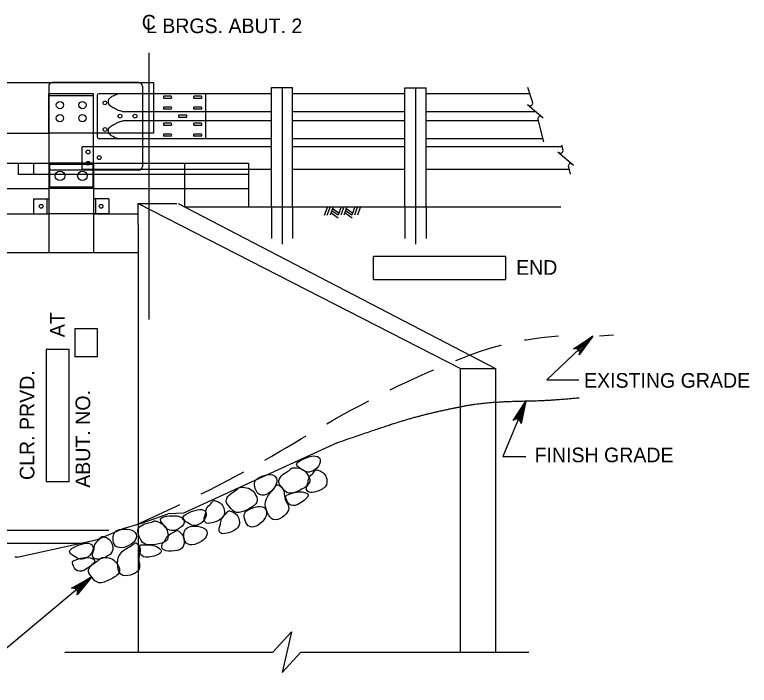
# Model space of a CAD drawing. Extents: x 638268 to 640277, y 295465 to 298435.
# Drawn here: x 638721.7 to 638872.6, y 297975.3 to 298112.9 of the extents above; entities that cross this region are included whole.
import ezdxf

# ---------------------------------------------------------------- set-up
doc = ezdxf.new("R2010")
doc.units = 0
for name, color, linetype in [('2', 7, 'Continuous'), ('3', 7, 'Continuous'), ('4', 7, 'Continuous'), ('8', 7, 'Continuous'), ('Level 25', 7, 'Continuous')]:
    doc.layers.add(name, color=color, linetype=linetype)

msp = doc.modelspace()

# ---------------------------------------------------------------- linework, layer by layer
at = {"layer": '2'}
for p, q in [((638577.23, 298099.02), (638750.23, 298099.02)), ((638747.15, 298099.02), (638729.45, 298099.02)), ((638750.23, 298099.02), (638750.23, 298096.71)), ((638728.68, 298098.25), (638728.68, 298096.7)), ((638747.92, 298098.25), (638747.92, 298096.71)), ((638737.91, 298096.7), (638728.68, 298096.7)), ((638728.68, 298088.62), (638728.68, 298096.7)), ((638737.91, 298096.32), (638728.68, 298096.32)), ((638737.91, 298082.46), (638737.91, 298096.7)), ((638738.65, 298096.35), (638738.65, 298087.85)), ((638750.23, 298096.72), (638739.02, 298096.72)), ((638747.92, 298096.71), (638747.92, 298087.47)), ((638760.82, 298096.72), (638750.23, 298096.72)), ((638750.23, 298096.7), (638750.23, 298088.62)), ((638753.84, 298096.21), (638752.36, 298096.21)), ((638753.84, 298095.75), (638752.36, 298095.75)), ((638760.01, 298096.21), (638758.54, 298096.21)), ((638760.01, 298095.75), (638758.54, 298095.75)), ((638760.88, 298096.72), (638760.88, 298087.48)), ((638774.46, 298096.72), (638760.88, 298096.72)), ((638801.85, 298096.72), (638778.78, 298096.72)), ((638827.47, 298096.72), (638806.18, 298096.72)), ((638753.84, 298093.99), (638752.36, 298093.99)), ((638760.01, 298093.99), (638758.54, 298093.99)), ((638750.23, 298093.02), (638744.48, 298093.02)), ((638774.46, 298093.02), (638750.23, 298093.02)), ((638753.84, 298093.53), (638752.36, 298093.53)), ((638760.01, 298093.53), (638758.54, 298093.53)), ((638801.85, 298093.02), (638778.78, 298093.02)), ((638828.79, 298093.02), (638806.18, 298093.02)), ((638750.23, 298091.18), (638744.48, 298091.18)), ((638774.46, 298091.18), (638750.23, 298091.18)), ((638756.93, 298092.33), (638755.45, 298092.33)), ((638756.93, 298091.87), (638755.45, 298091.87)), ((638801.85, 298091.18), (638778.78, 298091.18)), ((638829.24, 298091.18), (638806.18, 298091.18)), ((638753.84, 298090.67), (638752.36, 298090.67)), ((638753.84, 298090.2), (638752.36, 298090.2)), ((638760.01, 298090.67), (638758.54, 298090.67)), ((638760.01, 298090.2), (638758.54, 298090.2)), ((638690.3, 298088.62), (638728.68, 298088.62)), ((638728.68, 298088.62), (638728.68, 298082.46)), ((638737.91, 298088.62), (638728.68, 298088.62)), ((638747.92, 298088.62), (638737.91, 298088.62)), ((638750.23, 298088.62), (638747.92, 298088.62)), ((638753.84, 298088.45), (638752.36, 298088.45)), ((638753.84, 298087.99), (638752.36, 298087.99)), ((638760.01, 298088.45), (638758.54, 298088.45)), ((638760.01, 298087.99), (638758.54, 298087.99)), ((638747.92, 298087.48), (638739.02, 298087.48)), ((638774.46, 298087.48), (638747.92, 298087.48)), ((638801.85, 298087.48), (638778.78, 298087.48)), ((638830.16, 298087.48), (638806.18, 298087.48)), ((638735.57, 298081.2), (638735.57, 298085.82)), ((638747.92, 298085.82), (638735.57, 298085.82)), ((638774.46, 298085.82), (638747.92, 298085.82)), ((638801.85, 298085.82), (638778.78, 298085.82)), ((638834.09, 298085.82), (638806.18, 298085.82)), ((638690.3, 298082.46), (638728.68, 298082.46)), ((638722.51, 298080.15), (638722.51, 298082.46)), ((638725.6, 298080.15), (638725.6, 298082.46)), ((638737.91, 298082.46), (638728.68, 298082.46)), ((638728.68, 298082.46), (638728.68, 298064.14)), ((638737.75, 298082.18), (638728.87, 298082.18)), ((638728.87, 298082.18), (638728.87, 298077.56)), ((638737.75, 298082.18), (638737.75, 298077.56)), ((638737.91, 298082.46), (638737.91, 298064.14)), ((638737.91, 298082.46), (638769.68, 298082.46)), ((638747.92, 298082.46), (638747.92, 298081.8)), ((638769.68, 298082.46), (638769.68, 298073.51)), ((638747.15, 298081.03), (638729.45, 298081.03)), ((638769.66, 298081.2), (638735.57, 298081.2)), ((638774.46, 298081.2), (638769.66, 298081.2)), ((638801.85, 298081.2), (638778.78, 298081.2)), ((638835.54, 298081.2), (638806.18, 298081.2)), ((638769.66, 298080.15), (638722.51, 298080.15)), ((638737.75, 298077.56), (638728.87, 298077.56)), ((638690.3, 298077.26), (638728.68, 298077.26)), ((638737.91, 298077.26), (638728.68, 298077.26)), ((638725.59, 298075.16), (638728.68, 298075.16)), ((638725.59, 298075.16), (638725.59, 298072.07)), ((638728.31, 298075.16), (638728.31, 298072.07)), ((638728.68, 298075.16), (638728.68, 298072.07)), ((638741.01, 298075.16), (638737.91, 298075.16)), ((638737.91, 298075.16), (638737.91, 298072.07)), ((638738.28, 298075.16), (638738.28, 298072.07)), ((638741.01, 298075.16), (638741.01, 298072.07)), ((638725.59, 298072.07), (638728.68, 298072.07)), ((638725.59, 298072.07), (638728.68, 298072.07)), ((638737.91, 298072.07), (638728.68, 298072.07)), ((638741.01, 298072.07), (638737.91, 298072.07)), ((638741.01, 298072.07), (638737.91, 298072.07))]:
    msp.add_line(p, q, dxfattribs=at)
for centre, radius in [((638730.99, 298094.4), 0.748), ((638735.61, 298094.4), 0.748), ((638740.23, 298094.84), 0.385), ((638743.33, 298092.11), 0.385), ((638746.41, 298092.11), 0.385), ((638730.99, 298091.7), 0.748), ((638735.61, 298091.7), 0.748), ((638740.25, 298089.38), 0.385), ((638736.76, 298084.77), 0.385), ((638739.07, 298083.61), 0.385), ((638736.76, 298082.46), 0.385), ((638731, 298079.86), 0.978), ((638735.61, 298079.86), 0.978), ((638727.14, 298073.62), 0.385), ((638739.45, 298073.62), 0.385)]:
    msp.add_circle(centre, radius, dxfattribs=at)
for centre, radius, start, end in [((638729.45, 298098.25), 0.77, 90, 180), ((638747.15, 298098.25), 0.77, 0, 90), ((638739.02, 298096.35), 0.369, 90, 180), ((638741.79, 298095.09), 0.916, 120.3532, 238.6149), ((638744.1, 298092.45), 4.42, 125.3229, 129.0151), ((638742.1, 298095.27), 0.955, 117.3798, 125.3229), ((638756.29, 298067.88), 31.8, 116.5749, 117.3798), ((638743.14, 298094.16), 2.42, 113.6547, 116.5749), ((638744.55, 298090.94), 5.93, 112.3149, 113.6547), ((638766.88, 298036.55), 64.73, 111.9093, 112.3149), ((638743.43, 298094.85), 1.88, 108.4934, 111.9093), ((638746.06, 298086.99), 10.17, 107.0234, 108.4934), ((638752.5, 298095.98), 0.269, 120.8559, 239.1441), ((638753.7, 298095.98), 0.269, 300.8559, 59.1441), ((638758.67, 298095.98), 0.269, 120.8559, 239.1441), ((638759.88, 298095.98), 0.269, 300.8559, 59.1441), ((638744.54, 298098.04), 4.94, 229.2007, 233.1182), ((638742.23, 298094.96), 1.09, 233.1182, 241.475), ((638929.3, 298439.15), 392.83, 241.475, 241.5275), ((638752.5, 298093.76), 0.269, 120.8559, 239.1441), ((638753.7, 298093.76), 0.269, 300.8559, 59.1441), ((638758.67, 298093.76), 0.269, 120.8559, 239.1441), ((638759.88, 298093.76), 0.269, 300.8559, 59.1441), ((638681.78, 297982.76), 126.36, 61.435, 61.5275), ((638687.17, 297992.66), 115.08, 61.2499, 61.435), ((638752.85, 298112.37), 21.45, 241.2499, 241.6785), ((638742.97, 298094.05), 0.644, 241.6785, 249.7671), ((638749.04, 298110.5), 18.18, 249.7671, 251.2889), ((638744.22, 298096.26), 3.14, 251.2889, 252.6389), ((638770.72, 298181.03), 91.96, 252.6389, 252.8885), ((638744.29, 298095.21), 2.16, 252.8885, 261.633), ((638744.71, 298098.05), 5.03, 261.633, 267.3571), ((638770.72, 298003.16), 91.96, 107.1115, 107.3611), ((638744.29, 298088.99), 2.16, 98.367, 107.1115), ((638744.71, 298086.15), 5.03, 92.6429, 98.367), ((638755.59, 298092.1), 0.269, 120.8559, 239.1441), ((638756.79, 298092.1), 0.269, 300.8559, 59.1441), ((638741.79, 298089.11), 0.916, 121.3851, 239.6468), ((638744.54, 298086.15), 4.94, 126.8818, 130.7993), ((638742.23, 298089.23), 1.09, 118.525, 126.8818), ((638929.3, 297745.04), 392.83, 118.4725, 118.525), ((638681.78, 298201.44), 126.36, 298.4725, 298.565), ((638687.17, 298191.53), 115.08, 298.565, 298.7501), ((638752.85, 298071.83), 21.45, 118.3215, 118.7501), ((638742.97, 298090.15), 0.644, 110.2329, 118.3215), ((638749.04, 298073.7), 18.18, 108.7111, 110.2329), ((638744.22, 298087.94), 3.14, 107.3611, 108.7111), ((638752.5, 298090.44), 0.269, 120.8559, 239.1441), ((638753.7, 298090.44), 0.269, 300.8559, 59.1441), ((638758.67, 298090.44), 0.269, 120.8559, 239.1441), ((638759.88, 298090.44), 0.269, 300.8559, 59.1441), ((638744.1, 298091.75), 4.42, 230.9849, 234.6771), ((638742.1, 298088.93), 0.955, 234.6771, 242.6202), ((638756.29, 298116.32), 31.8, 242.6202, 243.4251), ((638752.5, 298088.22), 0.269, 120.8559, 239.1441), ((638753.7, 298088.22), 0.269, 300.8559, 59.1441), ((638758.67, 298088.22), 0.269, 120.8559, 239.1441), ((638759.88, 298088.22), 0.269, 300.8559, 59.1441), ((638739.02, 298087.85), 0.369, 180, 270), ((638743.14, 298090.04), 2.42, 243.4251, 246.3453), ((638744.55, 298093.26), 5.93, 246.3453, 247.6851), ((638766.88, 298147.65), 64.73, 247.6851, 248.0907), ((638743.43, 298089.35), 1.88, 248.0907, 251.5066), ((638746.06, 298097.2), 10.17, 251.5066, 252.9766), ((638729.45, 298081.8), 0.77, 180, 270), ((638747.15, 298081.8), 0.77, 270, 0)]:
    msp.add_arc(centre, radius, start, end, dxfattribs=at)
at = {"layer": '3'}
for p, q in [((638774.46, 298097.98), (638778.78, 298097.98)), ((638774.46, 298073.51), (638774.46, 298097.98)), ((638776.62, 298097.98), (638776.62, 298065.82)), ((638778.78, 298073.51), (638778.78, 298097.98)), ((638801.85, 298097.9), (638806.18, 298097.9)), ((638801.85, 298073.51), (638801.85, 298097.9)), ((638804.01, 298097.9), (638804.01, 298065.82)), ((638806.18, 298073.51), (638806.18, 298097.9)), ((638827.03, 298098.08), (638828.05, 298094.93)), ((638826.98, 298094.54), (638830.24, 298091.8)), ((638829.16, 298091.46), (638830.31, 298086.87)), ((638833.97, 298086.2), (638834.29, 298085.21)), ((638833.22, 298084.82), (638836.48, 298082.08)), ((638756.67, 298073.51), (638756.67, 298082.46)), ((638835.4, 298081.74), (638835.78, 298080.23)), ((638737.91, 298077.26), (638769.68, 298077.26)), ((638747.07, 298074.23), (638813.28, 298040.35)), ((638747.07, 298069.91), (638747.07, 298074.23)), ((638747.07, 298074.23), (638755, 298074.23)), ((638755.28, 298074.23), (638820.41, 298040.35)), ((638756.67, 298073.51), (638833.87, 298073.51)), ((638756.67, 298073.51), (638822.22, 298073.51)), ((638774.46, 298073.51), (638774.46, 298067.03)), ((638778.78, 298073.51), (638778.78, 298067.03)), ((638785.94, 298073.51), (638785.27, 298071.76)), ((638785.94, 298073.51), (638785.27, 298071.76)), ((638786.49, 298073.52), (638785.82, 298071.76)), ((638786.49, 298073.52), (638785.82, 298071.76)), ((638787.13, 298073.53), (638786.46, 298071.78)), ((638787.13, 298073.53), (638786.46, 298071.78)), ((638786.99, 298073.19), (638788.28, 298072.29)), ((638786.99, 298073.19), (638788.28, 298072.29)), ((638788.75, 298073.53), (638788.1, 298071.8)), ((638788.75, 298073.53), (638788.1, 298071.8)), ((638789.3, 298073.54), (638788.64, 298071.81)), ((638789.3, 298073.54), (638788.64, 298071.81)), ((638789.93, 298073.54), (638789.28, 298071.82)), ((638789.93, 298073.54), (638789.28, 298071.82)), ((638789.8, 298073.2), (638791.09, 298072.3)), ((638789.8, 298073.2), (638791.09, 298072.3)), ((638791.56, 298073.54), (638790.91, 298071.81)), ((638791.56, 298073.54), (638790.91, 298071.81)), ((638792.11, 298073.55), (638791.45, 298071.82)), ((638792.11, 298073.55), (638791.45, 298071.82)), ((638792.74, 298073.55), (638792.09, 298071.83)), ((638792.74, 298073.55), (638792.09, 298071.83)), ((638801.85, 298073.51), (638801.85, 298067.03)), ((638806.18, 298073.51), (638806.18, 298067.03)), ((638690.3, 298072.07), (638728.68, 298072.07)), ((638737.91, 298072.07), (638747.07, 298072.07)), ((638737.91, 298072.07), (638747.07, 298072.07)), ((638786.66, 298072.31), (638788.16, 298071.27)), ((638786.66, 298072.31), (638788.16, 298071.27)), ((638786.83, 298072.76), (638788.12, 298071.86)), ((638786.83, 298072.76), (638788.12, 298071.86)), ((638789.47, 298072.32), (638790.97, 298071.28)), ((638789.47, 298072.32), (638790.97, 298071.28)), ((638789.64, 298072.77), (638790.93, 298071.88)), ((638789.64, 298072.77), (638790.93, 298071.88)), ((638747.07, 298069.91), (638747.07, 298008.41)), ((638568.29, 298064.14), (638747.07, 298064.14)), ((638840.43, 298046.95), (638830.95, 298038.02)), ((638813.28, 298040.35), (638820.41, 298040.35)), ((638813.28, 298032.5), (638813.28, 298040.35)), ((638820.41, 298040.35), (638820.41, 298033.41)), ((638830.95, 298038.02), (638837.55, 298038.02)), ((638826.67, 298033.67), (638821.91, 298022.27)), ((638813.28, 297982.13), (638813.28, 298032.5)), ((638820.41, 298033.41), (638820.41, 297982.13)), ((638787.93, 298025.12), (638756.34, 298010.63)), ((638821.91, 298022.27), (638826.68, 298022.27)), ((638756.34, 298010.63), (638753.19, 298010.55)), ((638747.07, 298008.41), (638747.07, 297982.13)), ((638574.64, 298004.52), (638735.37, 298004.52)), ((638774.68, 297982.13), (638778.53, 297986.3)), ((638778.53, 297986.3), (638776.6, 297977.96)), ((638732, 297982.13), (638774.68, 297982.13)), ((638776.6, 297977.96), (638780.44, 297982.13)), ((638780.44, 297982.13), (638827.27, 297982.13))]:
    msp.add_line(p, q, dxfattribs=at)
for points in [[(638837.89, 298045.23), (638838.56, 298044.51), (638840.38, 298046.89)], [(638825.08, 298031.13), (638825.99, 298030.75), (638826.67, 298033.67)]]:
    msp.add_lwpolyline(points, close=True, dxfattribs=at)
for centre, radius, start, end in [((638827.54, 298094.77), 0.533, 227.8504, 17.8504), ((638829.68, 298091.58), 0.533, 49.9832, 192.5218), ((638829.68, 298091.58), 0.533, 49.9832, 49.9972), ((638833.78, 298085.05), 0.533, 227.8504, 17.8504), ((638835.92, 298081.86), 0.533, 49.9832, 192.5218), ((638835.92, 298081.86), 0.533, 49.9832, 49.9972), ((638721.7, 297990.13), 11.48, 87.4213, 90)]:
    msp.add_arc(centre, radius, start, end, dxfattribs=at)
for points, degree in [([(638787.93, 298025.12), (638795.7, 298027.8), (638802.85, 298030.13), (638810, 298031.88), (638816.75, 298033.19), (638823.1, 298033.62), (638831.64, 298033.77), (638837.59, 298034.35)], 2), ([(638779.79, 298020.29), (638780.03, 298020.03), (638780.9, 298019.47), (638782, 298018.83), (638783.99, 298019.77), (638784.75, 298021.7), (638783.66, 298022.6), (638781.64, 298022.16), (638779.46, 298021.02), (638779.55, 298020.54), (638779.79, 298020.29)], 3), ([(638771.15, 298017.39), (638770.87, 298017.02), (638770.91, 298016.18), (638771.54, 298014.35), (638773.38, 298014.22), (638775.13, 298015.84), (638775.83, 298017.48), (638774.86, 298018.81), (638772.59, 298018.41), (638771.43, 298017.76), (638771.15, 298017.39)], 3), ([(638778.38, 298019.73), (638778.32, 298019.64), (638777.99, 298019.36), (638776.4, 298018.44), (638775.61, 298017.01), (638776.61, 298015.96), (638777.82, 298014.33), (638780.39, 298015.33), (638782.61, 298016.74), (638782.07, 298018.34), (638781.28, 298019.47), (638779.68, 298020.08), (638778.33, 298019.87), (638778.44, 298019.81), (638778.38, 298019.73)], 3), ([(638781.91, 298016.79), (638781.85, 298016.49), (638781.54, 298016.12), (638781.7, 298014.9), (638783.04, 298014.73), (638785.93, 298015.98), (638785.84, 298017.73), (638785.33, 298018.83), (638784.07, 298019.54), (638783.41, 298019.57), (638783.11, 298018.96), (638781.94, 298017.93), (638781.98, 298017.09), (638781.91, 298016.79)], 3), ([(638767.6, 298015.75), (638767.55, 298015.66), (638767.22, 298015.38), (638765.63, 298014.46), (638764.84, 298013.03), (638765.84, 298011.98), (638767.04, 298010.35), (638769.62, 298011.35), (638771.84, 298012.76), (638771.29, 298014.36), (638770.5, 298015.49), (638768.9, 298016.09), (638767.55, 298015.89), (638767.66, 298015.83), (638767.6, 298015.75)], 3), ([(638775.47, 298016.42), (638775.33, 298016.33), (638775.22, 298015.87), (638772.96, 298013.56), (638773.21, 298011.35), (638774.61, 298008.77), (638776.81, 298009.78), (638778.22, 298011.29), (638777.75, 298012.66), (638777, 298013.68), (638777.14, 298015.51), (638776.05, 298016.41), (638775.61, 298016.51), (638775.47, 298016.42)], 3), ([(638777.92, 298014.5), (638777.5, 298014.36), (638777.2, 298014.25), (638777.91, 298012.2), (638779.63, 298012.02), (638782.75, 298014.49), (638780.9, 298015.02), (638779.72, 298015.12), (638778.34, 298014.65), (638777.92, 298014.5)], 3), ([(638760.89, 298010.49), (638760.82, 298010.19), (638760.52, 298009.83), (638760.67, 298008.6), (638762.01, 298008.44), (638764.91, 298009.68), (638764.81, 298011.44), (638764.3, 298012.54), (638763.04, 298013.25), (638762.39, 298013.28), (638762.09, 298012.66), (638760.92, 298011.63), (638760.95, 298010.79), (638760.89, 298010.49)], 3), ([(638756.4, 298009.3), (638756.64, 298009.05), (638757.51, 298008.49), (638758.61, 298007.85), (638760.6, 298008.79), (638761.36, 298010.72), (638760.27, 298011.62), (638758.25, 298011.18), (638756.07, 298010.04), (638756.16, 298009.56), (638756.4, 298009.3)], 3), ([(638763.95, 298008.37), (638763.89, 298008.07), (638763.59, 298007.71), (638763.74, 298006.48), (638765.08, 298006.31), (638767.98, 298007.56), (638767.88, 298009.32), (638767.37, 298010.42), (638766.11, 298011.13), (638765.45, 298011.16), (638765.16, 298010.55), (638763.98, 298009.51), (638764.02, 298008.68), (638763.95, 298008.37)], 3), ([(638769.05, 298010.84), (638768.77, 298010.47), (638768.81, 298009.63), (638769.44, 298007.8), (638771.28, 298007.67), (638773.03, 298009.29), (638773.72, 298010.93), (638772.75, 298012.26), (638770.48, 298011.86), (638769.33, 298011.21), (638769.05, 298010.84)], 3), ([(638751.7, 298009.05), (638751.85, 298008.73), (638752.49, 298007.92), (638753.33, 298006.96), (638755.51, 298007.2), (638756.85, 298008.78), (638756.11, 298009.99), (638754.06, 298010.23), (638751.63, 298009.86), (638751.56, 298009.37), (638751.7, 298009.05)], 3), ([(638750.19, 298008.98), (638750.11, 298008.92), (638749.7, 298008.76), (638747.9, 298008.41), (638746.69, 298007.31), (638747.29, 298005.99), (638747.9, 298004.06), (638750.66, 298004.17), (638753.23, 298004.78), (638753.23, 298006.48), (638752.85, 298007.79), (638751.53, 298008.89), (638750.18, 298009.13), (638750.27, 298009.04), (638750.19, 298008.98)], 3), ([(638742.51, 298007), (638742.12, 298006.74), (638741.89, 298005.93), (638741.89, 298004), (638743.58, 298003.28), (638745.76, 298004.24), (638746.95, 298005.56), (638746.47, 298007.14), (638744.19, 298007.49), (638742.89, 298007.26), (638742.51, 298007)], 3), ([(638752.57, 298005.05), (638752.41, 298004.79), (638752.01, 298004.54), (638751.76, 298003.33), (638752.97, 298002.74), (638756.11, 298002.98), (638756.6, 298004.67), (638756.47, 298005.88), (638755.51, 298006.96), (638754.9, 298007.2), (638754.42, 298006.71), (638752.97, 298006.12), (638752.73, 298005.32), (638752.57, 298005.05)], 3), ([(638757.02, 298007.61), (638756.64, 298007.35), (638756.4, 298006.54), (638756.4, 298004.61), (638758.1, 298003.89), (638760.28, 298004.85), (638761.47, 298006.17), (638760.99, 298007.75), (638758.71, 298008.1), (638757.41, 298007.87), (638757.02, 298007.61)], 3), ([(638737.95, 298003.12), (638737.89, 298002.82), (638737.58, 298002.46), (638737.74, 298001.23), (638739.08, 298001.06), (638741.97, 298002.31), (638741.88, 298004.07), (638741.37, 298005.17), (638740.11, 298005.88), (638739.45, 298005.91), (638739.15, 298005.29), (638737.98, 298004.26), (638738.02, 298003.42), (638737.95, 298003.12)], 3), ([(638733.15, 298002.39), (638733.39, 298002.14), (638734.26, 298001.58), (638735.37, 298000.94), (638737.35, 298001.88), (638738.11, 298003.81), (638737.02, 298004.71), (638735, 298004.27), (638732.82, 298003.13), (638732.91, 298002.65), (638733.15, 298002.39)], 3), ([(638746.45, 298004.55), (638746.29, 298004.51), (638746.04, 298004.11), (638743.15, 298002.67), (638742.67, 298000.49), (638743.15, 297997.59), (638745.56, 297997.84), (638747.38, 297998.8), (638747.38, 298000.25), (638747, 298001.46), (638747.74, 298003.15), (638747, 298004.36), (638746.61, 298004.59), (638746.45, 298004.55)], 3), ([(638748.06, 298004.19), (638747.61, 298004.19), (638747.29, 298004.19), (638747.29, 298002.01), (638748.87, 298001.29), (638752.62, 298002.61), (638751.05, 298003.71), (638749.96, 298004.19), (638748.5, 298004.19), (638748.06, 298004.19)], 3), ([(638734.09, 298001.03), (638733.67, 298000.89), (638733.37, 298000.78), (638734.08, 297998.73), (638735.8, 297998.55), (638738.92, 298001.02), (638737.08, 298001.54), (638735.89, 298001.65), (638734.51, 298001.17), (638734.09, 298001.03)], 3), ([(638739.33, 298001.35), (638739.27, 298001.27), (638738.94, 298000.98), (638737.35, 298000.06), (638736.56, 297998.63), (638737.56, 297997.58), (638738.76, 297995.95), (638741.34, 297996.96), (638743.56, 297998.37), (638743.01, 297999.97), (638742.23, 298001.09), (638740.62, 298001.7), (638739.28, 298001.49), (638739.38, 298001.44), (638739.33, 298001.35)], 3)]:
    msp.add_open_spline(points, degree=degree, dxfattribs=at)
at = {"layer": '4'}
for p, q in [((638749.23, 298105.1), (638749.23, 298050.42)), ((638822.56, 298063.29), (638795.41, 298063.29)), ((638795.41, 298058.59), (638795.41, 298063.29)), ((638822.56, 298058.59), (638822.56, 298063.29)), ((638795.41, 298058.59), (638822.56, 298058.59)), ((638734.02, 298048.47), (638734.02, 298042.73)), ((638738.73, 298048.47), (638734.02, 298048.47)), ((638738.73, 298042.73), (638738.73, 298048.47)), ((638728.18, 298044.21), (638728.18, 298017.07)), ((638732.88, 298044.21), (638728.18, 298044.21)), ((638732.88, 298017.07), (638732.88, 298044.21)), ((638738.73, 298042.73), (638734.02, 298042.73)), ((638732.88, 298017.07), (638728.18, 298017.07)), ((638710.19, 298007.16), (638741.01, 298007.16)), ((638737.53, 297997.57), (638710.89, 297975.34))]:
    msp.add_line(p, q, dxfattribs=at)
for points in [[(638840.43, 298046.95), (638837.64, 298043.12), (638837.73, 298043.54), (638837.65, 298043.9), (638837.48, 298044.16), (638837.22, 298044.35), (638836.87, 298044.45), (638836.44, 298044.39), (638840.43, 298046.95), (638836.87, 298044.45), (638837.22, 298044.35), (638840.43, 298046.95), (638837.48, 298044.16), (638837.65, 298043.9), (638840.43, 298046.95), (638837.73, 298043.54)], [(638826.67, 298033.67), (638825.68, 298029.03), (638825.59, 298029.46), (638825.37, 298029.75), (638825.1, 298029.92), (638824.79, 298029.99), (638824.44, 298029.94), (638824.07, 298029.7), (638826.67, 298033.67), (638824.44, 298029.94), (638824.79, 298029.99), (638826.67, 298033.67), (638825.1, 298029.92), (638825.37, 298029.75), (638826.67, 298033.67), (638825.59, 298029.46)], [(638722.22, 298001.6), (638738.73, 298005.27), (638743.99, 298007.51), (638747.76, 298008.6), (638753.19, 298010.55)], [(638737.53, 297997.57), (638734.51, 297993.91), (638734.63, 297994.33), (638734.57, 297994.69), (638734.41, 297994.96), (638734.17, 297995.17), (638733.83, 297995.29), (638733.39, 297995.25), (638737.53, 297997.57), (638733.83, 297995.29), (638734.17, 297995.17), (638737.53, 297997.57), (638734.41, 297994.96), (638734.57, 297994.69), (638737.53, 297997.57), (638734.63, 297994.33)]]:
    msp.add_lwpolyline(points, dxfattribs=at)
msp.add_lwpolyline([(638734.95, 297996.05), (638735.58, 297995.3), (638737.53, 297997.57)], close=True, dxfattribs=at)
at = {"layer": '8'}
for p, q in [((638826.4, 298046.19), (638826.74, 298046.25)), ((638826.74, 298046.25), (638829.83, 298046.68)), ((638829.83, 298046.68), (638833.36, 298047.04)), ((638841.82, 298047.04), (638844.65, 298047.23)), ((638817.18, 298043.81), (638819.3, 298044.51)), ((638819.3, 298044.51), (638821.55, 298045.15)), ((638821.55, 298045.15), (638821.59, 298045.16)), ((638813.04, 298042.26), (638815.11, 298043.06)), ((638815.11, 298043.06), (638817.18, 298043.81)), ((638812.29, 298041.97), (638813.04, 298042.26)), ((638806.73, 298039.66), (638807.74, 298040.09)), ((638802.54, 298037.76), (638804.63, 298038.73)), ((638804.63, 298038.73), (638806.73, 298039.66)), ((638798.8, 298035.97), (638800.47, 298036.78)), ((638800.47, 298036.78), (638802.54, 298037.76)), ((638792.48, 298032.71), (638794.41, 298033.74)), ((638790.59, 298031.69), (638792.48, 298032.71)), ((638786.99, 298029.68), (638788.76, 298030.67)), ((638788.76, 298030.67), (638790.59, 298031.69)), ((638785.79, 298028.99), (638786.99, 298029.68)), ((638780.61, 298025.95), (638781.54, 298026.51)), ((638777.63, 298024.19), (638779.13, 298025.08)), ((638779.13, 298025.08), (638780.61, 298025.95)), ((638774.51, 298022.37), (638776.11, 298023.29)), ((638776.11, 298023.29), (638777.63, 298024.19)), ((638773.05, 298021.53), (638774.51, 298022.37)), ((638766.81, 298018.09), (638768.75, 298019.14)), ((638764.37, 298016.8), (638766.81, 298018.09)), ((638761.62, 298015.4), (638764.37, 298016.8)), ((638760.01, 298014.61), (638761.62, 298015.4)), ((638751.1, 298010.33), (638755.04, 298012.18)), ((638755.04, 298012.18), (638755.59, 298012.45)), ((638746.67, 298008.29), (638751.1, 298010.33))]:
    msp.add_line(p, q, dxfattribs=at)
at = {"layer": 'Level 25'}
for p, q in [((638728.68, 298096.7), (638728.68, 298081.8)), ((638747.92, 298087.47), (638747.92, 298082.46))]:
    msp.add_line(p, q, dxfattribs=at)

# ---------------------------------------------------------------- texts
at = {"layer": '4'}
for s, p in [('C', (638747.8, 298109.89)), ('L BRGS. ABUT. 2', (638748.66, 298109.15)), ('END', (638824.66, 298059.57)), ('EXISTING GRADE', (638838.62, 298036.4)), ('FINISH GRADE', (638828.46, 298021.11))]:
    msp.add_text(s, height=3, dxfattribs=at).set_placement(p)
for s, p in [('AT', (638731.94, 298046.76)), ('CLR. PRVD.', (638725.74, 298017.46)), ('ABUT. NO. ', (638737.2, 298015.86))]:
    msp.add_text(s, height=3, rotation=90, dxfattribs=at).set_placement(p)

doc.saveas('drawing.dxf')
